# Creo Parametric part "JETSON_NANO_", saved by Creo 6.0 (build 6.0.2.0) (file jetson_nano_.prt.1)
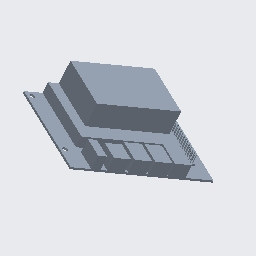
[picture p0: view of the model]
Units: millimeter Newton Second (mmNs); MM, TONNE, SECS

Created from: INLBS_PART_SOLID.PRT

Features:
  1. datum plane "RIGHT"
  2. datum plane "TOP"
  3. datum plane "FRONT"
  4. coordinate system
  5. sketch "Sketch 1"
  6. extrusion "Extrude 1"
  7. sketch "Sketch 2"
  8. extrusion "Extrude 2"
  9. sketch "Sketch 3"
  10. pattern "Pattern 1"
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
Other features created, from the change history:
  extrusion "Extrude 3"
  extrusion "Extrude 3 [2, 1]"
  extrusion "Extrude 3 [3, 1]"
  extrusion "Extrude 3 [4, 1]"
  extrusion "Extrude 3 [5, 1]"
  extrusion "Extrude 3 [6, 1]"
  extrusion "Extrude 3 [7, 1]"
  extrusion "Extrude 3 [8, 1]"
  extrusion "Extrude 3 [9, 1]"
  extrusion "Extrude 3 [10, 1]"
  extrusion "Extrude 3 [11, 1]"
  extrusion "Extrude 3 [12, 1]"
  extrusion "Extrude 3 [13, 1]"
  extrusion "Extrude 3 [14, 1]"
  extrusion "Extrude 3 [15, 1]"
  extrusion "Extrude 3 [16, 1]"
  extrusion "Extrude 3 [17, 1]"
  extrusion "Extrude 3 [18, 1]"
  extrusion "Extrude 3 [19, 1]"
  extrusion "Extrude 3 [20, 1]"
  extrusion "Extrude 3 [1, 2]"
  extrusion "Extrude 3 [2, 2]"
  extrusion "Extrude 3 [3, 2]"
  extrusion "Extrude 3 [4, 2]"
  extrusion "Extrude 3 [5, 2]"
  extrusion "Extrude 3 [6, 2]"
  extrusion "Extrude 3 [7, 2]"
  extrusion "Extrude 3 [8, 2]"
  extrusion "Extrude 3 [9, 2]"
  extrusion "Extrude 3 [10, 2]"
  extrusion "Extrude 3 [11, 2]"
  extrusion "Extrude 3 [12, 2]"
  extrusion "Extrude 3 [13, 2]"
  extrusion "Extrude 3 [14, 2]"
  extrusion "Extrude 3 [15, 2]"
  extrusion "Extrude 3 [16, 2]"
  extrusion "Extrude 3 [17, 2]"
  extrusion "Extrude 3 [18, 2]"
  extrusion "Extrude 3 [19, 2]"
  extrusion "Extrude 3 [20, 2]"
  sketch "Sketch 4"
  extrusion "Extrude 4"
  sketch "Sketch 5"
  extrusion "Extrude 5"
  sketch "Sketch 6"
  extrusion "Extrude 6"
  sketch "Sketch 7"
  extrusion "Extrude 7"

Surfaces: 77 plane, 44 cylinder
